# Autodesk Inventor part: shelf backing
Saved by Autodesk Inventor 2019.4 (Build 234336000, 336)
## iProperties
Created: 2020-09
Part Number: shelf backing
Material: Generic
Document SubType Name: Modeling
Designer: Administrator
Density: 1 g/cm^3
Appearance: Default
Title: shelf backing
Author: Administrator
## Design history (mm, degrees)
feature "Body1"
body "Solid1"
